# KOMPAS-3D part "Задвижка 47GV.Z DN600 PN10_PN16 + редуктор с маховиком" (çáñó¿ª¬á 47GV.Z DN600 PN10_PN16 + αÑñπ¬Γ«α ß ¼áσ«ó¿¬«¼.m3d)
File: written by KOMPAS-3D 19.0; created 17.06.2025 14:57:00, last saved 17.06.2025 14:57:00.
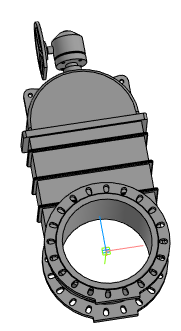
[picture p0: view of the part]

Document properties: Полное имя файла: Задвижка 47GV.Z DN600 PN10_PN16 + редуктор с маховиком.a3d

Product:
- Part/product: Задвижка 47GV.Z DN600 PN10_PN16 + редуктор с маховиком
    Масса: 1785.62

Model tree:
1. Операция без истории:1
